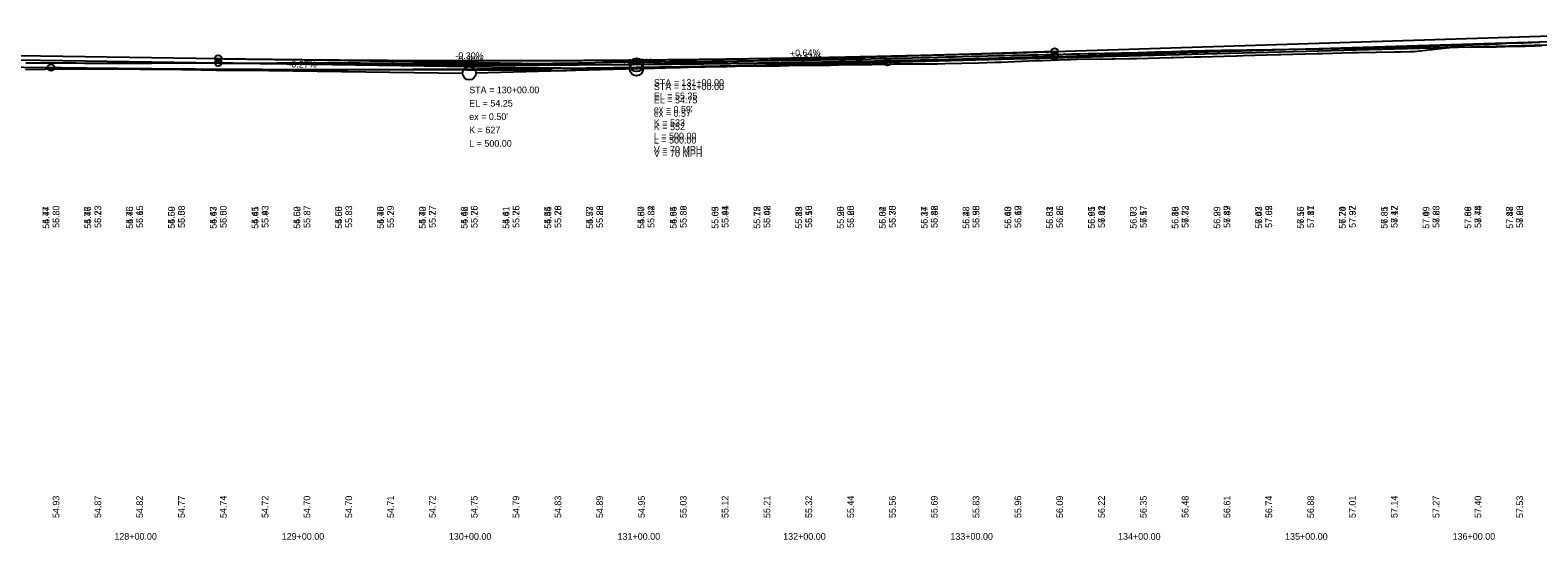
# Model space of a CAD drawing. Extents: x 3880794 to 3915434, y 287517 to 300173.
# Drawn here: x 3893276 to 3894177, y 296520 to 296825 of the extents above; entities that cross this region are included whole.
import ezdxf

# ---------------------------------------------------------------- set-up
doc = ezdxf.new("R2010")
doc.units = 0
for name, color, linetype in [('Level 1', 7, 'Continuous'), ('Level 2', 7, 'Continuous'), ('Level 30', 7, 'Continuous'), ('Level 31', 7, 'Continuous'), ('Level 32', 7, 'Continuous')]:
    doc.layers.add(name, color=color, linetype=linetype)

msp = doc.modelspace()

# ---------------------------------------------------------------- linework, layer by layer
at = {"layer": 'Level 1'}
for p, q in [((3893788.3, 296805.57), (3894288.3, 296818.69)), ((3893888.3, 296809.08), (3894288.3, 296821.19)), ((3893138.3, 296809.01), (3893388.3, 296805.26)), ((3893888.3, 296809.08), (3893642.3, 296801.63)), ((3893088.3, 296805.15), (3893288.3, 296802.42)), ((3893288.3, 296802.42), (3893534.3, 296799.06)), ((3893388.3, 296805.26), (3893634.3, 296801.57)), ((3893788.3, 296805.57), (3893542.3, 296799.11))]:
    msp.add_line(p, q, dxfattribs=at)
for points in [[(3893669.36, 296802.55), (3893689.62, 296803.02), (3893692.38, 296803.08), (3893697.25, 296803.16), (3893717.36, 296803.43), (3893717.91, 296803.44), (3893723.83, 296803.52), (3893728.8, 296803.59), (3893729.44, 296803.59), (3893749.54, 296803.88), (3893754.07, 296803.89), (3893758.79, 296803.96), (3893778.91, 296804.27), (3893782.25, 296804.37), (3893787.13, 296804.44), (3893791.99, 296804.57), (3893812.25, 296804.6), (3893814.09, 296804.65), (3893817.97, 296804.65), (3893822.7, 296804.76), (3893842.96, 296805.3), (3893852.58, 296805.55), (3893856.33, 296805.6), (3893876.8, 296806.54), (3893881.26, 296806.58), (3893895.7, 296807.26), (3893897.58, 296807.31), (3893901.71, 296807.41), (3893922.58, 296807.59), (3893923.85, 296807.64), (3893932.92, 296807.72), (3893937.12, 296807.87), (3893957.96, 296808.41), (3893959.31, 296808.44), (3893971.74, 296808.76), (3893975.61, 296808.84), (3893996.93, 296809.43), (3893997.36, 296809.44), (3894001.02, 296809.56), (3894022.07, 296810.14), (3894023.47, 296810.19), (3894045.15, 296810.76), (3894048.45, 296810.88), (3894066.25, 296811.34), (3894069.41, 296811.45), (3894069.8, 296811.46), (3894091.32, 296811.84), (3894095.07, 296811.88), (3894100.53, 296811.98), (3894103.1, 296811.99), (3894124.28, 296814.49), (3894125.35, 296814.74), (3894137.06, 296814.69), (3894139.83, 296814.73), (3894151.34, 296814.85), (3894152.35, 296814.86), (3894162.94, 296815.12), (3894163.79, 296815.14), (3894167.7, 296815.25), (3894169.37, 296815.29), (3894171.61, 296815.36), (3894175.52, 296815.48), (3894179.43, 296815.61)], [(3893273.08, 296801.23), (3893296.01, 296801.54), (3893308.17, 296801.71), (3893310.7, 296801.64), (3893333.33, 296801.57), (3893334.17, 296801.55), (3893341.35, 296801.53), (3893343.54, 296801.52), (3893366.46, 296801.17), (3893366.89, 296801.17), (3893368.9, 296801.17), (3893387.24, 296800.89), (3893387.69, 296800.89), (3893410.72, 296800.77), (3893412.71, 296800.8), (3893419.67, 296800.76), (3893420.16, 296800.77), (3893443.34, 296800.89), (3893445.15, 296800.9), (3893445.5, 296800.9), (3893452.43, 296800.93), (3893454.26, 296800.91), (3893477.42, 296801.17), (3893477.87, 296801.17), (3893485.82, 296801.26), (3893487.82, 296801.27), (3893510.9, 296801.25), (3893511.21, 296801.25), (3893512.39, 296801.25), (3893513.18, 296801.25), (3893536.6, 296801.05), (3893537.45, 296801.05), (3893544.7, 296800.99), (3893545.67, 296800.98), (3893546.72, 296800.96), (3893566.5, 296800.75), (3893567.65, 296800.74), (3893570.59, 296800.72), (3893583.62, 296800.63), (3893587.71, 296800.54), (3893590.46, 296800.47), (3893596.51, 296800.66), (3893599.23, 296800.74), (3893607.2, 296801.33), (3893609.39, 296801.52), (3893630.08, 296802.01), (3893632.9, 296801.96), (3893635.54, 296802.02), (3893639.96, 296802.18), (3893660.46, 296802.41), (3893661.24, 296802.43), (3893664.67, 296802.47), (3893669.36, 296802.55)]]:
    msp.add_lwpolyline(points, dxfattribs=at)
for centre in [(3893538.3, 296799.01), (3893638.3, 296801.51)]:
    msp.add_circle(centre, 4, dxfattribs=at)
for points in [[(3893388.3, 296805.26), (3893398.3, 296805.11), (3893408.3, 296804.98), (3893418.3, 296804.85), (3893428.3, 296804.73), (3893438.3, 296804.62), (3893448.3, 296804.52), (3893458.3, 296804.43), (3893468.3, 296804.35), (3893478.3, 296804.27), (3893488.3, 296804.21), (3893498.3, 296804.15), (3893508.3, 296804.11), (3893518.3, 296804.07), (3893528.3, 296804.04), (3893538.3, 296804.03), (3893548.3, 296804.02), (3893558.3, 296804.02), (3893568.3, 296804.02), (3893578.3, 296804.04), (3893588.3, 296804.07), (3893598.3, 296804.1), (3893608.3, 296804.15), (3893618.3, 296804.2), (3893628.3, 296804.26), (3893638.3, 296804.34), (3893648.3, 296804.42), (3893658.3, 296804.51), (3893668.3, 296804.61), (3893678.3, 296804.71), (3893688.3, 296804.83), (3893698.3, 296804.96), (3893708.3, 296805.09), (3893718.3, 296805.24), (3893728.3, 296805.39), (3893738.3, 296805.55), (3893748.3, 296805.72), (3893758.3, 296805.91), (3893768.3, 296806.1), (3893778.3, 296806.29), (3893788.3, 296806.5), (3893798.3, 296806.72), (3893808.3, 296806.94), (3893818.3, 296807.18), (3893828.3, 296807.42), (3893838.3, 296807.68), (3893848.3, 296807.94), (3893858.3, 296808.21), (3893868.3, 296808.49), (3893878.3, 296808.78), (3893888.3, 296809.08)], [(3893288.3, 296802.42), (3893298.3, 296802.29), (3893308.3, 296802.16), (3893318.3, 296802.04), (3893328.3, 296801.94), (3893338.3, 296801.84), (3893348.3, 296801.74), (3893358.3, 296801.66), (3893368.3, 296801.58), (3893378.3, 296801.51), (3893388.3, 296801.45), (3893398.3, 296801.4), (3893408.3, 296801.36), (3893418.3, 296801.32), (3893428.3, 296801.29), (3893438.3, 296801.27), (3893448.3, 296801.26), (3893458.3, 296801.25), (3893468.3, 296801.25), (3893478.3, 296801.27), (3893488.3, 296801.28), (3893498.3, 296801.31), (3893508.3, 296801.35), (3893518.3, 296801.39), (3893528.3, 296801.44), (3893538.3, 296801.5), (3893548.3, 296801.57), (3893558.3, 296801.64), (3893568.3, 296801.73), (3893578.3, 296801.82), (3893588.3, 296801.92), (3893598.3, 296802.02), (3893608.3, 296802.14), (3893618.3, 296802.26), (3893628.3, 296802.39), (3893638.3, 296802.53), (3893648.3, 296802.68), (3893658.3, 296802.83), (3893668.3, 296802.99), (3893678.3, 296803.16), (3893688.3, 296803.34), (3893698.3, 296803.53), (3893708.3, 296803.72), (3893718.3, 296803.93), (3893728.3, 296804.14), (3893738.3, 296804.36), (3893748.3, 296804.58), (3893758.3, 296804.82), (3893768.3, 296805.06), (3893778.3, 296805.31), (3893788.3, 296805.57)]]:
    msp.add_spline(points, degree=3, dxfattribs=at)
at = {"layer": 'Level 2'}
for p, q in [((3893888.3, 296811.99), (3894289.29, 296824.8)), ((3893138.3, 296811.51), (3893388.3, 296807.76)), ((3893888.3, 296811.99), (3893642.29, 296804.13)), ((3893388.3, 296807.76), (3893634.3, 296804.07))]:
    msp.add_line(p, q, dxfattribs=at)
for points in [[(3893538.3, 296804.86), (3893543.3, 296804.84), (3893548.3, 296804.83), (3893553.3, 296804.83), (3893558.3, 296804.81), (3893563.3, 296804.8), (3893568.3, 296804.86), (3893573.3, 296804.93), (3893578.3, 296804.92), (3893583.3, 296804.9), (3893588.3, 296804.96), (3893593.3, 296805.03), (3893598.3, 296805.09), (3893603.3, 296805.19), (3893608.3, 296805.3), (3893613.3, 296805.41), (3893618.3, 296805.53), (3893623.3, 296805.65), (3893628.3, 296805.75), (3893633.3, 296805.75), (3893638.3, 296805.76), (3893643.3, 296805.79), (3893648.3, 296805.81), (3893653.3, 296805.88), (3893658.3, 296805.97), (3893663.3, 296805.99), (3893668.3, 296806.02), (3893673.3, 296806.04), (3893678.3, 296806.11), (3893683.3, 296806.17), (3893688.3, 296806.23), (3893693.3, 296806.28), (3893698.3, 296806.34), (3893703.3, 296806.4), (3893708.3, 296806.46), (3893713.3, 296806.53), (3893718.3, 296806.62), (3893723.3, 296806.69), (3893728.3, 296806.76), (3893733.3, 296806.84), (3893738.3, 296806.91), (3893743.3, 296807), (3893748.3, 296807.07), (3893753.3, 296807.14), (3893758.3, 296807.2), (3893763.3, 296807.28), (3893768.3, 296807.38), (3893773.3, 296807.49), (3893778.3, 296807.61), (3893783.3, 296807.72), (3893788.3, 296807.84), (3893793.3, 296807.95), (3893798.3, 296808.06), (3893803.3, 296808.17), (3893808.3, 296808.33), (3893813.3, 296808.48), (3893818.3, 296808.61), (3893823.3, 296808.74), (3893828.3, 296808.89), (3893833.3, 296809.02), (3893838.3, 296809.14), (3893843.3, 296809.27), (3893848.3, 296809.41), (3893853.3, 296809.53), (3893858.3, 296809.66), (3893863.3, 296809.76), (3893868.3, 296809.83), (3893873.3, 296809.95), (3893878.3, 296810.07), (3893883.3, 296810.19), (3893888.3, 296810.29), (3893893.3, 296810.4), (3893898.3, 296810.51), (3893903.3, 296810.61), (3893908.3, 296810.72), (3893913.3, 296810.82), (3893918.3, 296810.93), (3893923.3, 296811.04), (3893928.3, 296811.15), (3893933.3, 296811.25), (3893938.3, 296811.4), (3893943.3, 296811.57), (3893948.3, 296811.71), (3893953.3, 296811.88), (3893958.3, 296812.05), (3893963.3, 296812.22), (3893968.3, 296812.39), (3893973.3, 296812.5), (3893978.3, 296812.57), (3893983.3, 296812.65), (3893988.3, 296812.72), (3893993.3, 296812.79), (3893998.3, 296812.86), (3894003.3, 296812.93), (3894008.3, 296813), (3894013.3, 296813.09), (3894018.3, 296813.17), (3894023.3, 296813.25), (3894028.3, 296813.34), (3894033.3, 296813.42), (3894038.3, 296813.51)], [(3894038.3, 296813.51), (3894043.3, 296813.59), (3894048.3, 296813.68), (3894053.3, 296813.76), (3894058.3, 296813.85), (3894063.3, 296813.93), (3894068.3, 296814.03), (3894073.3, 296814.15), (3894078.3, 296814.28), (3894083.3, 296814.39), (3894088.3, 296814.51), (3894093.3, 296814.64), (3894098.3, 296814.76), (3894103.3, 296814.88), (3894108.3, 296815.01), (3894113.3, 296815.18), (3894118.3, 296815.36), (3894123.3, 296815.54), (3894128.3, 296815.71), (3894133.3, 296815.89), (3894138.3, 296816.06), (3894143.3, 296816.24), (3894148.3, 296816.44), (3894153.3, 296816.67), (3894158.3, 296816.9), (3894163.3, 296817.11), (3894168.3, 296817.26), (3894173.3, 296817.4), (3894178.3, 296817.55)], [(3893273.3, 296805.13), (3893278.3, 296805.13), (3893283.3, 296805.13), (3893288.3, 296805.13), (3893293.3, 296805.13), (3893298.3, 296805.13), (3893303.3, 296805.13), (3893308.3, 296805.1), (3893313.3, 296805.06), (3893318.3, 296805.02), (3893323.3, 296805.02), (3893328.3, 296805.02), (3893333.3, 296805), (3893338.3, 296805), (3893343.3, 296805), (3893348.3, 296805.09), (3893353.3, 296805.18), (3893358.3, 296805.26), (3893363.3, 296805.26), (3893368.3, 296805.26), (3893373.3, 296805.24), (3893378.3, 296805.19), (3893383.3, 296805.14), (3893388.3, 296805.12), (3893393.3, 296805.1), (3893398.3, 296805.06), (3893403.3, 296805.04), (3893408.3, 296805.02), (3893413.3, 296805.01), (3893418.3, 296805.09), (3893423.3, 296805.16), (3893428.3, 296805.22), (3893433.3, 296805.25), (3893438.3, 296805.28), (3893443.3, 296805.24), (3893448.3, 296805.2), (3893453.3, 296805.22), (3893458.3, 296805.25), (3893463.3, 296805.27), (3893468.3, 296805.21), (3893473.3, 296805.16), (3893478.3, 296805.11), (3893483.3, 296805.06), (3893488.3, 296805.02), (3893493.3, 296804.97), (3893498.3, 296804.92), (3893503.3, 296804.87), (3893508.3, 296804.83), (3893513.3, 296804.87), (3893518.3, 296804.9), (3893523.3, 296804.91), (3893528.3, 296804.9), (3893533.3, 296804.88), (3893538.3, 296804.86)]]:
    msp.add_lwpolyline(points, dxfattribs=at)
for centre, radius in [((3893388.3, 296807.76), 2), ((3893888.3, 296811.99), 2), ((3893638.3, 296804.01), 4)]:
    msp.add_circle(centre, radius, dxfattribs=at)
msp.add_spline([(3893388.3, 296807.76), (3893398.3, 296807.61), (3893408.3, 296807.48), (3893418.3, 296807.35), (3893428.3, 296807.23), (3893438.3, 296807.12), (3893448.3, 296807.03), (3893458.3, 296806.94), (3893468.3, 296806.86), (3893478.3, 296806.79), (3893488.3, 296806.73), (3893498.3, 296806.68), (3893508.3, 296806.63), (3893518.3, 296806.6), (3893528.3, 296806.58), (3893538.3, 296806.56), (3893548.3, 296806.56), (3893558.3, 296806.56), (3893568.3, 296806.58), (3893578.3, 296806.6), (3893588.3, 296806.63), (3893598.3, 296806.68), (3893608.3, 296806.73), (3893618.3, 296806.79), (3893628.3, 296806.86), (3893638.3, 296806.94), (3893648.3, 296807.03), (3893658.3, 296807.13), (3893668.3, 296807.24), (3893678.3, 296807.36), (3893688.3, 296807.48), (3893698.3, 296807.62), (3893708.3, 296807.76), (3893718.3, 296807.92), (3893728.3, 296808.08), (3893738.3, 296808.26), (3893748.3, 296808.44), (3893758.3, 296808.63), (3893768.3, 296808.84), (3893778.3, 296809.05), (3893788.3, 296809.27), (3893798.3, 296809.5), (3893808.3, 296809.74), (3893818.3, 296809.99), (3893828.3, 296810.25), (3893838.3, 296810.51), (3893848.3, 296810.79), (3893858.3, 296811.08), (3893868.3, 296811.37), (3893878.3, 296811.68), (3893888.3, 296811.99)], degree=3, dxfattribs=at)
at = {"layer": 'Level 31'}
for centre in [(3893888.3, 296809.08), (3893288.3, 296802.42), (3893388.3, 296805.26), (3893788.3, 296805.57)]:
    msp.add_circle(centre, 2, dxfattribs=at)

# ---------------------------------------------------------------- texts
at = {"layer": 'Level 2'}
for s, rotation, p in [('-0.30%', 359.14063, (3893529.96, 296807.63)), ('+0.64%', 1.82966, (3893730.09, 296808.94)), ('56.30', 90, (3893293.3, 296706.43)), ('56.23', 90, (3893318.3, 296706.43)), ('56.15', 90, (3893343.3, 296706.43)), ('56.08', 90, (3893368.3, 296706.43)), ('56.00', 90, (3893393.3, 296706.43)), ('55.93', 90, (3893418.3, 296706.43)), ('55.87', 90, (3893443.3, 296706.43)), ('55.83', 90, (3893468.3, 296706.43)), ('55.79', 90, (3893493.3, 296706.43)), ('55.77', 90, (3893518.3, 296706.43)), ('55.76', 90, (3893543.3, 296706.43)), ('55.76', 90, (3893568.3, 296706.43)), ('55.78', 90, (3893593.3, 296706.43)), ('55.80', 90, (3893618.3, 296706.43)), ('55.84', 90, (3893649, 296706.43)), ('55.89', 90, (3893668.3, 296706.43)), ('55.94', 90, (3893693.3, 296706.43)), ('56.02', 90, (3893718.3, 296706.43)), ('56.10', 90, (3893743.3, 296706.43)), ('56.20', 90, (3893768.3, 296706.43)), ('56.30', 90, (3893793.3, 296706.43)), ('56.42', 90, (3893818.3, 296706.43)), ('56.55', 90, (3893843.3, 296706.43)), ('56.69', 90, (3893868.3, 296706.43)), ('56.85', 90, (3893893.3, 296706.43)), ('57.01', 90, (3893918.3, 296706.43)), ('57.17', 90, (3893943.3, 296706.43)), ('57.33', 90, (3893968.3, 296706.43)), ('57.49', 90, (3893993.3, 296706.43)), ('57.65', 90, (3894018.3, 296706.43)), ('57.81', 90, (3894043.3, 296706.43)), ('57.97', 90, (3894068.3, 296706.43)), ('58.12', 90, (3894093.3, 296706.43)), ('58.28', 90, (3894118.3, 296706.43)), ('58.44', 90, (3894143.3, 296706.43)), ('58.60', 90, (3894168.3, 296706.43))]:
    msp.add_text(s, height=4, rotation=rotation, dxfattribs=at).set_placement(p)
for s, p in [('STA = 131+00.00', (3893648.68, 296791.43)), ('EL = 55.25', (3893648.68, 296783.43)), ("ex = 0.59'", (3893648.68, 296775.43)), ('K = 533', (3893648.68, 296767.43)), ('V = 70 MPH', (3893648.68, 296751.43)), ('L = 500.00', (3893648.68, 296759.43)), ('128+00.00', (3893326.14, 296519.76)), ('129+00.00', (3893426.2, 296519.76)), ('130+00.00', (3893526.11, 296519.76)), ('131+00.00', (3893626.99, 296519.76)), ('132+00.00', (3893725.98, 296519.76)), ('133+00.00', (3893825.95, 296519.76)), ('134+00.00', (3893926.17, 296519.76)), ('135+00.00', (3894026.05, 296519.76)), ('136+00.00', (3894126.17, 296519.76))]:
    msp.add_text(s, height=4, dxfattribs=at).set_placement(p)
at = {"layer": 'Level 30'}
for s, p in [('54.74', (3893287.3, 296705.91)), ('54.77', (3893312.3, 296705.91)), ('54.76', (3893337.3, 296705.91)), ('54.69', (3893362.3, 296705.91)), ('54.63', (3893387.3, 296705.91)), ('54.61', (3893412.3, 296705.91)), ('54.62', (3893437.3, 296705.91)), ('54.65', (3893462.3, 296705.91)), ('54.70', (3893487.3, 296705.91)), ('54.70', (3893512.3, 296705.91)), ('54.66', (3893537.3, 296705.91)), ('54.61', (3893562.3, 296705.91)), ('54.55', (3893587.3, 296705.91)), ('54.77', (3893612.3, 296705.91)), ('54.87', (3893643, 296705.91)), ('54.94', (3893662.3, 296705.91)), ('55.05', (3893687.3, 296705.91)), ('55.12', (3893712.3, 296705.91)), ('55.19', (3893737.3, 296705.91)), ('55.25', (3893762.3, 296705.91)), ('55.34', (3893787.3, 296705.91)), ('55.37', (3893812.3, 296705.91)), ('55.48', (3893837.3, 296705.91)), ('55.63', (3893862.3, 296705.91)), ('55.83', (3893887.3, 296705.91)), ('55.95', (3893912.3, 296705.91)), ('56.03', (3893937.3, 296705.91)), ('56.16', (3893962.3, 296705.91)), ('56.29', (3893987.3, 296705.91)), ('56.43', (3894012.3, 296705.91)), ('56.56', (3894037.3, 296705.91)), ('56.70', (3894062.3, 296705.91)), ('56.81', (3894087.3, 296705.91)), ('57.09', (3894112.3, 296705.91)), ('57.39', (3894137.3, 296705.91)), ('57.48', (3894162.3, 296705.91))]:
    msp.add_text(s, height=4, rotation=90, dxfattribs=at).set_placement(p)
for s, p in [('128+00.00', (3893326.14, 296519.76)), ('128+00.00', (3893326.14, 296519.76)), ('128+00.00', (3893326.14, 296519.76)), ('129+00.00', (3893426.2, 296519.76)), ('129+00.00', (3893426.2, 296519.76)), ('129+00.00', (3893426.2, 296519.76)), ('130+00.00', (3893526.11, 296519.76)), ('130+00.00', (3893526.11, 296519.76)), ('130+00.00', (3893526.11, 296519.76)), ('131+00.00', (3893626.99, 296519.76)), ('131+00.00', (3893626.99, 296519.76)), ('131+00.00', (3893626.99, 296519.76)), ('132+00.00', (3893725.98, 296519.76)), ('132+00.00', (3893725.98, 296519.76)), ('132+00.00', (3893725.98, 296519.76)), ('133+00.00', (3893825.95, 296519.76)), ('133+00.00', (3893825.95, 296519.76)), ('133+00.00', (3893825.95, 296519.76)), ('134+00.00', (3893926.17, 296519.76)), ('134+00.00', (3893926.17, 296519.76)), ('134+00.00', (3893926.17, 296519.76)), ('135+00.00', (3894026.05, 296519.76)), ('135+00.00', (3894026.05, 296519.76)), ('135+00.00', (3894026.05, 296519.76)), ('136+00.00', (3894126.17, 296519.76)), ('136+00.00', (3894126.17, 296519.76)), ('136+00.00', (3894126.17, 296519.76))]:
    msp.add_text(s, height=4, dxfattribs=at).set_placement(p)
at = {"layer": 'Level 31'}
for s, rotation, p in [('-0.30%', 359.14063, (3893529.96, 296805.13)), ('+0.61%', 1.73426, (3893730.92, 296806.31)), ('-0.27%', 359.21837, (3893430.15, 296802.48)), ('+0.53%', 1.50367, (3893629.77, 296803.41)), ('55.80', 90, (3893293.3, 296706.43)), ('55.73', 90, (3893318.3, 296706.43)), ('55.65', 90, (3893343.3, 296706.43)), ('55.58', 90, (3893368.3, 296706.43)), ('55.50', 90, (3893393.3, 296706.43)), ('55.43', 90, (3893418.3, 296706.43)), ('55.37', 90, (3893443.3, 296706.43)), ('55.33', 90, (3893468.3, 296706.43)), ('55.29', 90, (3893493.3, 296706.43)), ('55.27', 90, (3893518.3, 296706.43)), ('55.25', 90, (3893543.3, 296706.43)), ('55.25', 90, (3893568.3, 296706.43)), ('55.26', 90, (3893593.3, 296706.43)), ('55.28', 90, (3893618.3, 296706.43)), ('55.32', 90, (3893649, 296706.43)), ('55.36', 90, (3893668.3, 296706.43)), ('55.41', 90, (3893693.3, 296706.43)), ('55.48', 90, (3893718.3, 296706.43)), ('55.56', 90, (3893743.3, 296706.43)), ('55.65', 90, (3893768.3, 296706.43)), ('55.75', 90, (3893793.3, 296706.43)), ('55.86', 90, (3893818.3, 296706.43)), ('55.98', 90, (3893843.3, 296706.43)), ('56.12', 90, (3893868.3, 296706.43)), ('56.26', 90, (3893893.3, 296706.43)), ('56.42', 90, (3893918.3, 296706.43)), ('56.57', 90, (3893943.3, 296706.43)), ('56.72', 90, (3893968.3, 296706.43)), ('56.87', 90, (3893993.3, 296706.43)), ('57.02', 90, (3894018.3, 296706.43)), ('57.17', 90, (3894043.3, 296706.43)), ('57.32', 90, (3894068.3, 296706.43)), ('57.47', 90, (3894093.3, 296706.43)), ('57.63', 90, (3894118.3, 296706.43)), ('57.78', 90, (3894143.3, 296706.43)), ('57.93', 90, (3894168.3, 296706.43)), ('54.93', 90, (3893293.3, 296532.76)), ('54.87', 90, (3893318.3, 296532.76)), ('54.82', 90, (3893343.3, 296532.76)), ('54.77', 90, (3893368.3, 296532.76)), ('54.74', 90, (3893393.3, 296532.76)), ('54.72', 90, (3893418.3, 296532.76)), ('54.70', 90, (3893443.3, 296532.76)), ('54.70', 90, (3893468.3, 296532.76)), ('54.71', 90, (3893493.3, 296532.76)), ('54.72', 90, (3893518.3, 296532.76)), ('54.75', 90, (3893543.3, 296532.76)), ('54.79', 90, (3893568.3, 296532.76)), ('54.83', 90, (3893593.3, 296532.76)), ('54.89', 90, (3893618.3, 296532.76)), ('54.95', 90, (3893643.3, 296532.76)), ('55.03', 90, (3893668.3, 296532.76)), ('55.12', 90, (3893693.3, 296532.76)), ('55.21', 90, (3893718.3, 296532.76)), ('55.32', 90, (3893743.3, 296532.76)), ('55.44', 90, (3893768.3, 296532.76)), ('55.56', 90, (3893793.3, 296532.76)), ('55.69', 90, (3893818.3, 296532.76)), ('55.83', 90, (3893843.3, 296532.76)), ('55.96', 90, (3893868.3, 296532.76)), ('56.09', 90, (3893893.3, 296532.76)), ('56.22', 90, (3893918.3, 296532.76)), ('56.35', 90, (3893943.3, 296532.76)), ('56.48', 90, (3893968.3, 296532.76)), ('56.61', 90, (3893993.3, 296532.76)), ('56.74', 90, (3894018.3, 296532.76)), ('56.88', 90, (3894043.3, 296532.76)), ('57.01', 90, (3894068.3, 296532.76)), ('57.14', 90, (3894093.3, 296532.76)), ('57.27', 90, (3894118.3, 296532.76)), ('57.40', 90, (3894143.3, 296532.76)), ('57.53', 90, (3894168.3, 296532.76))]:
    msp.add_text(s, height=4, rotation=rotation, dxfattribs=at).set_placement(p)
for s, p in [('STA = 130+00.00', (3893538.3, 296787.01)), ('STA = 131+00.00', (3893648.68, 296788.93)), ('EL = 54.25', (3893538.3, 296779.01)), ('EL = 54.75', (3893648.68, 296780.93)), ("ex = 0.50'", (3893538.3, 296771.01)), ("ex = 0.57'", (3893648.68, 296772.93)), ('K = 627', (3893538.3, 296763.01)), ('K = 552', (3893648.68, 296764.93)), ('L = 500.00', (3893538.3, 296755.01)), ('L = 500.00', (3893648.68, 296756.93)), ('V = 70 MPH', (3893648.68, 296748.93))]:
    msp.add_text(s, height=4, dxfattribs=at).set_placement(p)
at = {"layer": 'Level 32'}
for s, p in [('55.47', (3893287.3, 296705.91)), ('55.46', (3893312.3, 296705.91)), ('55.45', (3893337.3, 296705.91)), ('55.50', (3893362.3, 296705.91)), ('55.47', (3893387.3, 296705.91)), ('55.45', (3893412.3, 296705.91)), ('55.50', (3893437.3, 296705.91)), ('55.50', (3893462.3, 296705.91)), ('55.45', (3893487.3, 296705.91)), ('55.42', (3893512.3, 296705.91)), ('55.42', (3893537.3, 296705.91)), ('55.41', (3893562.3, 296705.91)), ('55.44', (3893587.3, 296705.91)), ('55.53', (3893612.3, 296705.91)), ('55.60', (3893643, 296705.91)), ('55.65', (3893662.3, 296705.91)), ('55.69', (3893687.3, 296705.91)), ('55.75', (3893712.3, 296705.91)), ('55.83', (3893737.3, 296705.91)), ('55.90', (3893762.3, 296705.91)), ('56.02', (3893787.3, 296705.91)), ('56.14', (3893812.3, 296705.91)), ('56.28', (3893837.3, 296705.91)), ('56.40', (3893862.3, 296705.91)), ('56.51', (3893887.3, 296705.91)), ('56.61', (3893912.3, 296705.91)), ('56.73', (3893937.3, 296705.91)), ('56.89', (3893962.3, 296705.91)), ('56.99', (3893987.3, 296705.91)), ('57.07', (3894012.3, 296705.91)), ('57.15', (3894037.3, 296705.91)), ('57.24', (3894062.3, 296705.91)), ('57.35', (3894087.3, 296705.91)), ('57.49', (3894112.3, 296705.91)), ('57.66', (3894137.3, 296705.91)), ('57.87', (3894162.3, 296705.91))]:
    msp.add_text(s, height=4, rotation=90, dxfattribs=at).set_placement(p)

doc.saveas('drawing.dxf')
